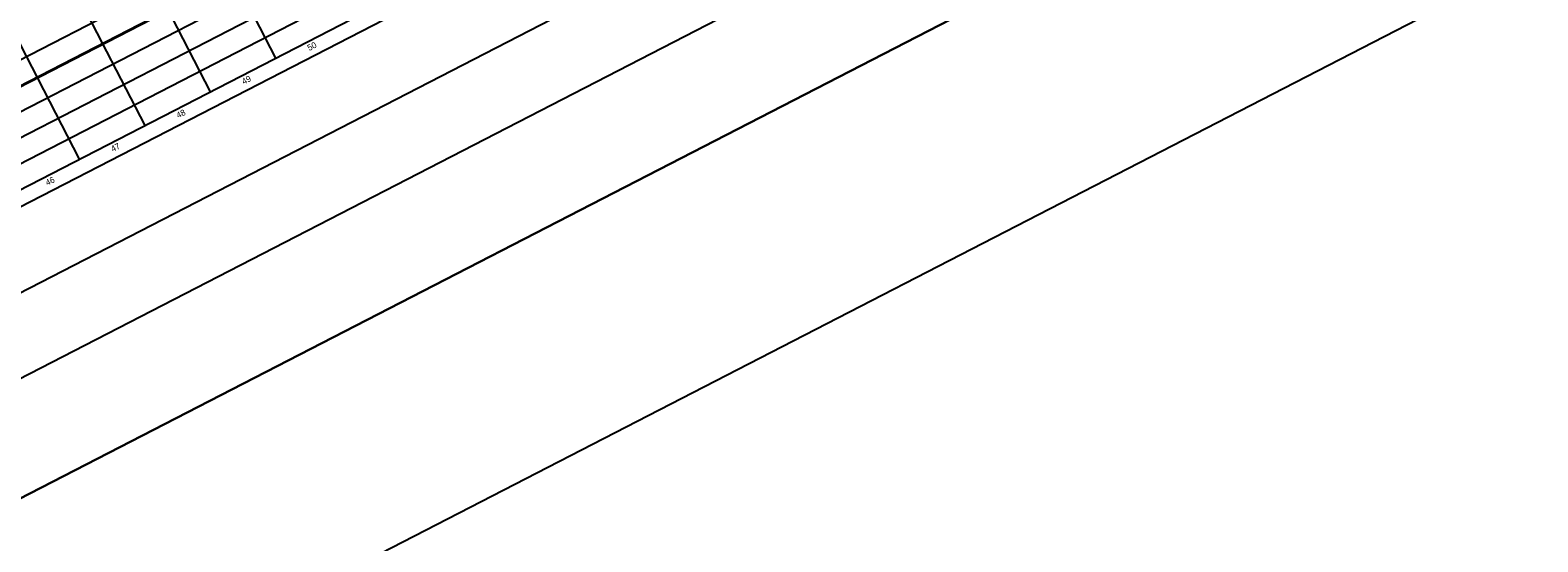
# Model space of a CAD drawing. Extents: x -886320 to -884760, y -1024172 to -1023483.
# Drawn here: x -885521.7 to -885274.6, y -1023980.9 to -1023897 of the extents above; entities that cross this region are included whole.
import ezdxf

# ---------------------------------------------------------------- set-up
doc = ezdxf.new("R2010")
doc.units = 0
for name, color, linetype in [('Stavajici_betonova_draha', 7, 'Continuous'), ('Stavajici_betonova_draha_Popis desky', 7, 'Continuous'), ('Stavajici_betonova_draha_Spára', 7, 'Continuous'), ('Stavajici_drahovy_system', 7, 'Continuous'), ('Stavajici_drahovy_system_osy', 7, 'Continuous'), ('Stavajici_drahovy_system_RWY_strip', 7, 'Continuous')]:
    doc.layers.add(name, color=color, linetype=linetype)

msp = doc.modelspace()

# ---------------------------------------------------------------- linework, layer by layer
at = {"layer": 'Stavajici_betonova_draha'}
msp.add_line((-886005.42, -1024171.44), (-884760.77, -1023530.47), dxfattribs=at)
msp.add_line((-886005.42, -1024171.44), (-884760.77, -1023530.47), dxfattribs=at)
at = {"layer": 'Stavajici_betonova_draha_Spára'}
for p, q in [((-886014.31, -1024154.72), (-884769.66, -1023513.75)), ((-886012.58, -1024158.09), (-884767.93, -1023517.12)), ((-886010.84, -1024161.46), (-884766.19, -1023520.48)), ((-886009.11, -1024164.82), (-884764.46, -1023523.85)), ((-886007.38, -1024168.19), (-884762.73, -1023527.21)), ((-886005.64, -1024171.55), (-884760.99, -1023530.58)), ((-885505.74, -1023854.49), (-885481.48, -1023901.62)), ((-885516.47, -1023860.02), (-885492.2, -1023907.14)), ((-885527.2, -1023865.55), (-885502.93, -1023912.67)), ((-885537.93, -1023871.07), (-885513.66, -1023918.19))]:
    msp.add_line(p, q, dxfattribs=at)
at = {"layer": 'Stavajici_drahovy_system'}
for p, q in [((-885721.56, -1024028.07), (-884864.53, -1023586.71)), ((-885726.12, -1024058.54), (-884837.08, -1023600.7)), ((-885744.78, -1024087.83), (-884802.4, -1023602.52)), ((-885728.75, -1024118.95), (-884786.38, -1023633.64))]:
    msp.add_line(p, q, dxfattribs=at)
at = {"layer": 'Stavajici_drahovy_system_osy'}
msp.add_line((-885731.84, -1024047.42), (-884842.81, -1023589.59), dxfattribs=at)
at = {"layer": 'Stavajici_drahovy_system_RWY_strip'}
for p, q in [((-885772.25, -1024034.49), (-884829.87, -1023549.18)), ((-884802.4, -1023602.52), (-885744.78, -1024087.83))]:
    msp.add_line(p, q, dxfattribs=at)

# ---------------------------------------------------------------- texts
at = {"layer": 'Stavajici_betonova_draha_Popis desky'}
for s, p in [('50', (-885475.96, -1023900.47)), ('49', (-885486.7, -1023905.99)), ('48', (-885497.43, -1023911.52)), ('47', (-885508.15, -1023917.04)), ('46', (-885518.88, -1023922.57))]:
    msp.add_text(s, height=1, rotation=27.2477, dxfattribs=at).set_placement(p)

doc.saveas('drawing.dxf')
